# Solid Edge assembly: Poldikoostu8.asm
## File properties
Author: Türk
Template: Iso Assembly.asm
Last saved by: Türk
Revision: 2
Application: Solid Edge
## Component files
Polt90x20.par
Mutter.par
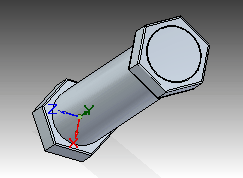
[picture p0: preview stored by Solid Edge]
